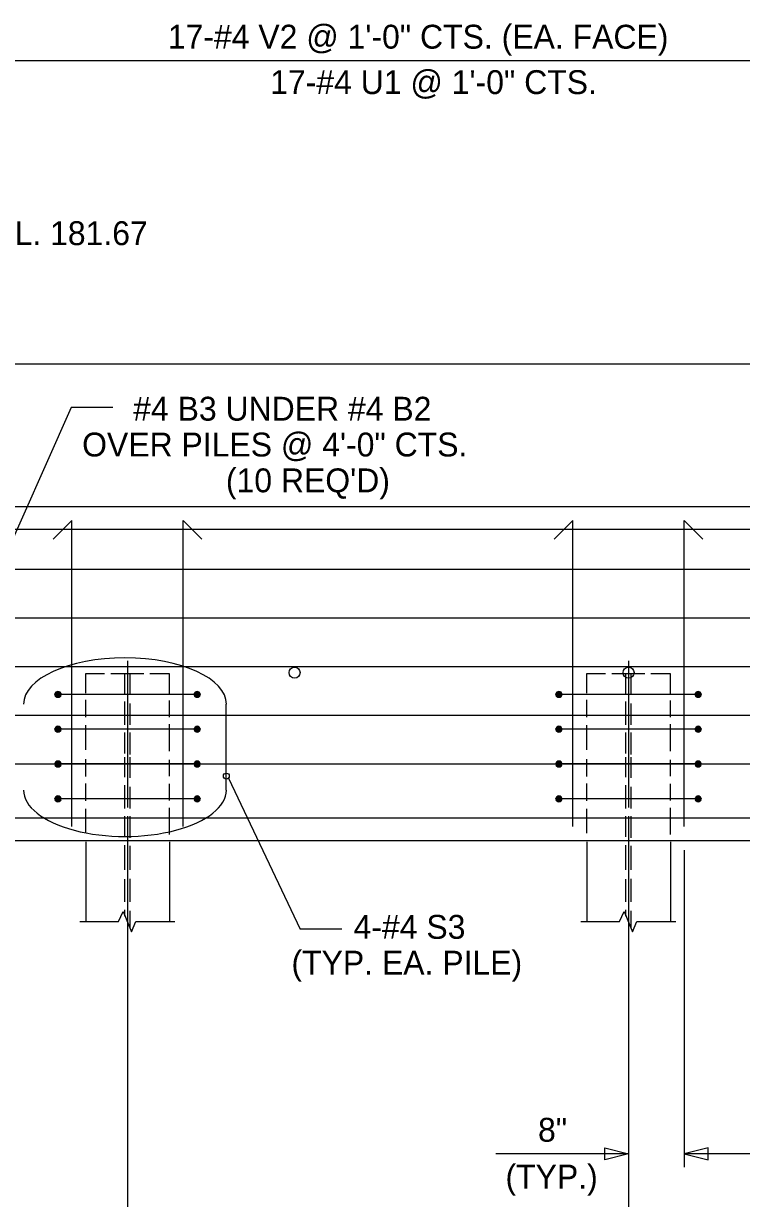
# Model space of a CAD drawing. Extents: x -41 to 251, y -169 to 237.
# Drawn here: x 105.52 to 114.12, y -40.94 to -26.87 of the extents above; entities that cross this region are included whole.
import ezdxf

# ---------------------------------------------------------------- set-up
doc = ezdxf.new("R2010")
doc.units = 0
for name, color, linetype in [('Arrowhead Terminators', 7, 'Continuous'), ('Arrowhead Terminators CELL', 7, 'Continuous'), ('Dimension Lines', 7, 'Continuous'), ('Dimension Lines CELL', 7, 'Continuous'), ('Mis Object Lines', 7, 'Continuous'), ('Rebar Lines', 7, 'Continuous'), ('Rebar Lines CELL', 7, 'Continuous'), ('Text', 7, 'Continuous')]:
    doc.layers.add(name, color=color, linetype=linetype)

msp = doc.modelspace()

# ---------------------------------------------------------------- linework, layer by layer
at = {"layer": 'Arrowhead Terminators'}
msp.add_lwpolyline([(113.716, -40.331), (113.43, -40.402), (113.716, -40.474)], close=True, dxfattribs=at)
at = {"layer": 'Arrowhead Terminators CELL'}
msp.add_lwpolyline([(112.763, -40.402), (112.477, -40.474), (112.477, -40.331)], close=True, dxfattribs=at)
at = {"layer": 'Dimension Lines'}
for p, q in [((102.846, -27.312), (118.763, -27.312)), ((106.087, -31.467), (104.763, -34.448)), ((106.587, -31.467), (106.087, -31.467)), ((107.946, -36.047), (107.946, -35.02)), ((107.973, -35.904), (108.831, -37.714)), ((106.763, -36.652), (106.763, -43.319)), ((112.763, -36.652), (112.763, -43.001)), ((113.43, -36.767), (113.43, -40.562)), ((109.331, -37.714), (108.831, -37.714)), ((112.763, -40.402), (111.175, -40.402)), ((118.096, -40.402), (113.43, -40.402))]:
    msp.add_line(p, q, dxfattribs=at)
for centre, start_param, end_param in [((106.732, -35.02), 3.141593, 6.283185), ((106.732, -36.047), 0, 3.141593)]:
    msp.add_ellipse(centre, major_axis=(-1.215, 0), ratio=0.457627, start_param=start_param, end_param=end_param, dxfattribs=at)
at = {"layer": 'Dimension Lines CELL'}
msp.add_circle((107.946, -35.88), 0.0353, dxfattribs=at)
at = {"layer": 'Mis Object Lines'}
for p, q in [((102.555, -30.944), (125.46, -30.944)), ((99.263, -32.652), (138.263, -32.652)), ((102.851, -36.652), (132.579, -36.652))]:
    msp.add_line(p, q, dxfattribs=at)
at = {"layer": 'Rebar Lines'}
for p, q in [((99.97, -32.923), (137.551, -32.923)), ((106.096, -32.819), (105.872, -33.043)), ((106.096, -36.485), (106.096, -32.819)), ((107.43, -36.485), (107.43, -32.819)), ((107.43, -32.819), (107.654, -33.043)), ((112.096, -32.819), (111.872, -33.043)), ((112.096, -36.485), (112.096, -32.819)), ((113.43, -36.485), (113.43, -32.819)), ((113.43, -32.819), (113.654, -33.043)), ((99.512, -33.402), (117.387, -33.402)), ((99.512, -33.986), (117.387, -33.986)), ((99.512, -34.569), (117.387, -34.569)), ((106.763, -34.501), (106.763, -36.257)), ((112.763, -34.501), (112.763, -36.257)), ((106.732, -34.895), (106.732, -34.652)), ((106.795, -34.901), (106.795, -34.652)), ((112.732, -34.895), (112.732, -34.652)), ((112.795, -34.901), (112.795, -34.652)), ((106.732, -35.267), (106.732, -34.988)), ((106.795, -35.267), (106.795, -35.011)), ((112.732, -35.267), (112.732, -34.988)), ((112.795, -35.267), (112.795, -35.011)), ((99.512, -35.152), (117.387, -35.152)), ((106.732, -35.609), (106.732, -35.36)), ((106.795, -35.621), (106.795, -35.36)), ((112.732, -35.609), (112.732, -35.36)), ((112.795, -35.621), (112.795, -35.36)), ((99.512, -35.735), (117.387, -35.735)), ((106.732, -35.895), (106.732, -35.652)), ((106.795, -35.901), (106.795, -35.652)), ((112.732, -35.895), (112.732, -35.652)), ((112.795, -35.901), (112.795, -35.652)), ((106.732, -36.267), (106.732, -35.988)), ((106.795, -36.267), (106.795, -36.011)), ((112.732, -36.267), (112.732, -35.988)), ((112.795, -36.267), (112.795, -36.011)), ((99.97, -36.381), (137.551, -36.381)), ((106.732, -36.609), (106.732, -36.36)), ((106.763, -36.362), (106.763, -36.652)), ((106.795, -36.621), (106.795, -36.36)), ((112.732, -36.609), (112.732, -36.36)), ((112.763, -36.362), (112.763, -36.652)), ((112.795, -36.621), (112.795, -36.36)), ((106.262, -36.669), (106.262, -37.621)), ((106.732, -37.004), (106.732, -36.708)), ((106.763, -36.722), (106.763, -37.928)), ((106.795, -37.004), (106.795, -36.714)), ((107.264, -36.669), (107.264, -37.621)), ((112.262, -36.669), (112.262, -37.621)), ((112.732, -37.004), (112.732, -36.708)), ((112.763, -36.722), (112.763, -37.928)), ((112.795, -37.004), (112.795, -36.714)), ((113.264, -36.669), (113.264, -37.621)), ((106.732, -37.388), (106.732, -37.115)), ((106.795, -37.388), (106.795, -37.109)), ((112.732, -37.388), (112.732, -37.115)), ((112.795, -37.388), (112.795, -37.109)), ((106.732, -37.556), (106.732, -37.481)), ((106.795, -37.705), (106.795, -37.492)), ((112.732, -37.556), (112.732, -37.481)), ((112.795, -37.705), (112.795, -37.492))]:
    msp.add_line(p, q, dxfattribs=at)
for points in [[(106.262, -34.886), (106.262, -34.652), (106.485, -34.652)], [(106.561, -34.652), (106.96, -34.652)], [(107.03, -34.652), (107.262, -34.652), (107.262, -34.899)], [(112.262, -34.886), (112.262, -34.652), (112.485, -34.652)], [(112.561, -34.652), (112.96, -34.652)], [(113.03, -34.652), (113.262, -34.652), (113.262, -34.899)], [(106.262, -35.176), (106.262, -34.968)], [(107.262, -34.974), (107.262, -35.173)], [(112.262, -35.176), (112.262, -34.968)], [(113.262, -34.974), (113.262, -35.173)], [(106.262, -35.564), (106.262, -35.272)], [(107.262, -35.259), (107.262, -35.58)], [(112.262, -35.564), (112.262, -35.272)], [(113.262, -35.259), (113.262, -35.58)], [(106.262, -35.886), (106.262, -35.678)], [(107.262, -35.684), (107.262, -35.883)], [(112.262, -35.886), (112.262, -35.678)], [(113.262, -35.684), (113.262, -35.883)], [(106.262, -36.176), (106.262, -35.968)], [(107.262, -35.974), (107.262, -36.173)], [(112.262, -36.176), (112.262, -35.968)], [(113.262, -35.974), (113.262, -36.173)], [(106.262, -36.564), (106.262, -36.272)], [(107.262, -36.259), (107.262, -36.58)], [(112.262, -36.564), (112.262, -36.272)], [(113.262, -36.259), (113.262, -36.58)], [(106.193, -37.622), (106.655, -37.622), (106.71, -37.502), (106.812, -37.747), (106.863, -37.622), (107.33, -37.622)], [(112.193, -37.622), (112.655, -37.622), (112.71, -37.502), (112.812, -37.747), (112.863, -37.622), (113.33, -37.622)]]:
    msp.add_lwpolyline(points, dxfattribs=at)
for centre in [(108.763, -34.641), (112.763, -34.641)]:
    msp.add_circle(centre, 0.066, dxfattribs=at)
at = {"layer": 'Rebar Lines CELL'}
for p, q in [((107.596, -34.902), (105.93, -34.902)), ((113.596, -34.902), (111.93, -34.902)), ((107.596, -35.319), (105.93, -35.319)), ((113.596, -35.319), (111.93, -35.319)), ((107.596, -35.735), (105.93, -35.735)), ((113.596, -35.735), (111.93, -35.735)), ((107.596, -36.152), (105.93, -36.152)), ((113.596, -36.152), (111.93, -36.152))]:
    msp.add_line(p, q, dxfattribs=at)
for points in [[(105.93, -34.867), (105.916, -34.87), (105.905, -34.877), (105.897, -34.889), (105.894, -34.902), (105.897, -34.916), (105.905, -34.927), (105.916, -34.935), (105.93, -34.937), (105.943, -34.935), (105.955, -34.927), (105.962, -34.916), (105.965, -34.902), (105.962, -34.889), (105.955, -34.877), (105.943, -34.87), (105.93, -34.867), (105.93, -34.902), (105.93, -34.937), (105.916, -34.935), (105.93, -34.902), (105.905, -34.927), (105.897, -34.916), (105.93, -34.902), (105.894, -34.902), (105.897, -34.889), (105.93, -34.902), (105.905, -34.877), (105.916, -34.87), (105.93, -34.902), (105.943, -34.87), (105.955, -34.877), (105.93, -34.902), (105.962, -34.889), (105.965, -34.902), (105.93, -34.902), (105.962, -34.916), (105.955, -34.927), (105.93, -34.902), (105.943, -34.935)], [(107.596, -34.867), (107.583, -34.87), (107.571, -34.877), (107.564, -34.889), (107.561, -34.902), (107.564, -34.916), (107.571, -34.927), (107.583, -34.935), (107.596, -34.937), (107.61, -34.935), (107.621, -34.927), (107.629, -34.916), (107.632, -34.902), (107.629, -34.889), (107.621, -34.877), (107.61, -34.87), (107.596, -34.867), (107.596, -34.902), (107.596, -34.937), (107.583, -34.935), (107.596, -34.902), (107.571, -34.927), (107.564, -34.916), (107.596, -34.902), (107.561, -34.902), (107.564, -34.889), (107.596, -34.902), (107.571, -34.877), (107.583, -34.87), (107.596, -34.902), (107.61, -34.87), (107.621, -34.877), (107.596, -34.902), (107.629, -34.889), (107.632, -34.902), (107.596, -34.902), (107.629, -34.916), (107.621, -34.927), (107.596, -34.902), (107.61, -34.935)], [(111.93, -34.867), (111.916, -34.87), (111.905, -34.877), (111.897, -34.889), (111.894, -34.902), (111.897, -34.916), (111.905, -34.927), (111.916, -34.935), (111.93, -34.937), (111.943, -34.935), (111.955, -34.927), (111.962, -34.916), (111.965, -34.902), (111.962, -34.889), (111.955, -34.877), (111.943, -34.87), (111.93, -34.867), (111.93, -34.902), (111.93, -34.937), (111.916, -34.935), (111.93, -34.902), (111.905, -34.927), (111.897, -34.916), (111.93, -34.902), (111.894, -34.902), (111.897, -34.889), (111.93, -34.902), (111.905, -34.877), (111.916, -34.87), (111.93, -34.902), (111.943, -34.87), (111.955, -34.877), (111.93, -34.902), (111.962, -34.889), (111.965, -34.902), (111.93, -34.902), (111.962, -34.916), (111.955, -34.927), (111.93, -34.902), (111.943, -34.935)], [(113.596, -34.867), (113.583, -34.87), (113.571, -34.877), (113.564, -34.889), (113.561, -34.902), (113.564, -34.916), (113.571, -34.927), (113.583, -34.935), (113.596, -34.937), (113.61, -34.935), (113.621, -34.927), (113.629, -34.916), (113.632, -34.902), (113.629, -34.889), (113.621, -34.877), (113.61, -34.87), (113.596, -34.867), (113.596, -34.902), (113.596, -34.937), (113.583, -34.935), (113.596, -34.902), (113.571, -34.927), (113.564, -34.916), (113.596, -34.902), (113.561, -34.902), (113.564, -34.889), (113.596, -34.902), (113.571, -34.877), (113.583, -34.87), (113.596, -34.902), (113.61, -34.87), (113.621, -34.877), (113.596, -34.902), (113.629, -34.889), (113.632, -34.902), (113.596, -34.902), (113.629, -34.916), (113.621, -34.927), (113.596, -34.902), (113.61, -34.935)], [(105.93, -35.284), (105.916, -35.286), (105.905, -35.294), (105.897, -35.305), (105.894, -35.319), (105.897, -35.332), (105.905, -35.344), (105.916, -35.351), (105.93, -35.354), (105.943, -35.351), (105.955, -35.344), (105.962, -35.332), (105.965, -35.319), (105.962, -35.305), (105.955, -35.294), (105.943, -35.286), (105.93, -35.284), (105.93, -35.319), (105.93, -35.354), (105.916, -35.351), (105.93, -35.319), (105.905, -35.344), (105.897, -35.332), (105.93, -35.319), (105.894, -35.319), (105.897, -35.305), (105.93, -35.319), (105.905, -35.294), (105.916, -35.286), (105.93, -35.319), (105.943, -35.286), (105.955, -35.294), (105.93, -35.319), (105.962, -35.305), (105.965, -35.319), (105.93, -35.319), (105.962, -35.332), (105.955, -35.344), (105.93, -35.319), (105.943, -35.351)], [(107.596, -35.284), (107.583, -35.286), (107.571, -35.294), (107.564, -35.305), (107.561, -35.319), (107.564, -35.332), (107.571, -35.344), (107.583, -35.351), (107.596, -35.354), (107.61, -35.351), (107.621, -35.344), (107.629, -35.332), (107.632, -35.319), (107.629, -35.305), (107.621, -35.294), (107.61, -35.286), (107.596, -35.284), (107.596, -35.319), (107.596, -35.354), (107.583, -35.351), (107.596, -35.319), (107.571, -35.344), (107.564, -35.332), (107.596, -35.319), (107.561, -35.319), (107.564, -35.305), (107.596, -35.319), (107.571, -35.294), (107.583, -35.286), (107.596, -35.319), (107.61, -35.286), (107.621, -35.294), (107.596, -35.319), (107.629, -35.305), (107.632, -35.319), (107.596, -35.319), (107.629, -35.332), (107.621, -35.344), (107.596, -35.319), (107.61, -35.351)], [(111.93, -35.284), (111.916, -35.286), (111.905, -35.294), (111.897, -35.305), (111.894, -35.319), (111.897, -35.332), (111.905, -35.344), (111.916, -35.351), (111.93, -35.354), (111.943, -35.351), (111.955, -35.344), (111.962, -35.332), (111.965, -35.319), (111.962, -35.305), (111.955, -35.294), (111.943, -35.286), (111.93, -35.284), (111.93, -35.319), (111.93, -35.354), (111.916, -35.351), (111.93, -35.319), (111.905, -35.344), (111.897, -35.332), (111.93, -35.319), (111.894, -35.319), (111.897, -35.305), (111.93, -35.319), (111.905, -35.294), (111.916, -35.286), (111.93, -35.319), (111.943, -35.286), (111.955, -35.294), (111.93, -35.319), (111.962, -35.305), (111.965, -35.319), (111.93, -35.319), (111.962, -35.332), (111.955, -35.344), (111.93, -35.319), (111.943, -35.351)], [(113.596, -35.284), (113.583, -35.286), (113.571, -35.294), (113.564, -35.305), (113.561, -35.319), (113.564, -35.332), (113.571, -35.344), (113.583, -35.351), (113.596, -35.354), (113.61, -35.351), (113.621, -35.344), (113.629, -35.332), (113.632, -35.319), (113.629, -35.305), (113.621, -35.294), (113.61, -35.286), (113.596, -35.284), (113.596, -35.319), (113.596, -35.354), (113.583, -35.351), (113.596, -35.319), (113.571, -35.344), (113.564, -35.332), (113.596, -35.319), (113.561, -35.319), (113.564, -35.305), (113.596, -35.319), (113.571, -35.294), (113.583, -35.286), (113.596, -35.319), (113.61, -35.286), (113.621, -35.294), (113.596, -35.319), (113.629, -35.305), (113.632, -35.319), (113.596, -35.319), (113.629, -35.332), (113.621, -35.344), (113.596, -35.319), (113.61, -35.351)], [(105.93, -35.7), (105.916, -35.703), (105.905, -35.711), (105.897, -35.722), (105.894, -35.735), (105.897, -35.749), (105.905, -35.76), (105.916, -35.768), (105.93, -35.771), (105.943, -35.768), (105.955, -35.76), (105.962, -35.749), (105.965, -35.735), (105.962, -35.722), (105.955, -35.711), (105.943, -35.703), (105.93, -35.7), (105.93, -35.735), (105.93, -35.771), (105.916, -35.768), (105.93, -35.735), (105.905, -35.76), (105.897, -35.749), (105.93, -35.735), (105.894, -35.735), (105.897, -35.722), (105.93, -35.735), (105.905, -35.711), (105.916, -35.703), (105.93, -35.735), (105.943, -35.703), (105.955, -35.711), (105.93, -35.735), (105.962, -35.722), (105.965, -35.735), (105.93, -35.735), (105.962, -35.749), (105.955, -35.76), (105.93, -35.735), (105.943, -35.768)], [(107.596, -35.7), (107.583, -35.703), (107.571, -35.711), (107.564, -35.722), (107.561, -35.735), (107.564, -35.749), (107.571, -35.76), (107.583, -35.768), (107.596, -35.771), (107.61, -35.768), (107.621, -35.76), (107.629, -35.749), (107.632, -35.735), (107.629, -35.722), (107.621, -35.711), (107.61, -35.703), (107.596, -35.7), (107.596, -35.735), (107.596, -35.771), (107.583, -35.768), (107.596, -35.735), (107.571, -35.76), (107.564, -35.749), (107.596, -35.735), (107.561, -35.735), (107.564, -35.722), (107.596, -35.735), (107.571, -35.711), (107.583, -35.703), (107.596, -35.735), (107.61, -35.703), (107.621, -35.711), (107.596, -35.735), (107.629, -35.722), (107.632, -35.735), (107.596, -35.735), (107.629, -35.749), (107.621, -35.76), (107.596, -35.735), (107.61, -35.768)], [(111.93, -35.7), (111.916, -35.703), (111.905, -35.711), (111.897, -35.722), (111.894, -35.735), (111.897, -35.749), (111.905, -35.76), (111.916, -35.768), (111.93, -35.771), (111.943, -35.768), (111.955, -35.76), (111.962, -35.749), (111.965, -35.735), (111.962, -35.722), (111.955, -35.711), (111.943, -35.703), (111.93, -35.7), (111.93, -35.735), (111.93, -35.771), (111.916, -35.768), (111.93, -35.735), (111.905, -35.76), (111.897, -35.749), (111.93, -35.735), (111.894, -35.735), (111.897, -35.722), (111.93, -35.735), (111.905, -35.711), (111.916, -35.703), (111.93, -35.735), (111.943, -35.703), (111.955, -35.711), (111.93, -35.735), (111.962, -35.722), (111.965, -35.735), (111.93, -35.735), (111.962, -35.749), (111.955, -35.76), (111.93, -35.735), (111.943, -35.768)], [(113.596, -35.7), (113.583, -35.703), (113.571, -35.711), (113.564, -35.722), (113.561, -35.735), (113.564, -35.749), (113.571, -35.76), (113.583, -35.768), (113.596, -35.771), (113.61, -35.768), (113.621, -35.76), (113.629, -35.749), (113.632, -35.735), (113.629, -35.722), (113.621, -35.711), (113.61, -35.703), (113.596, -35.7), (113.596, -35.735), (113.596, -35.771), (113.583, -35.768), (113.596, -35.735), (113.571, -35.76), (113.564, -35.749), (113.596, -35.735), (113.561, -35.735), (113.564, -35.722), (113.596, -35.735), (113.571, -35.711), (113.583, -35.703), (113.596, -35.735), (113.61, -35.703), (113.621, -35.711), (113.596, -35.735), (113.629, -35.722), (113.632, -35.735), (113.596, -35.735), (113.629, -35.749), (113.621, -35.76), (113.596, -35.735), (113.61, -35.768)], [(105.93, -36.117), (105.916, -36.12), (105.905, -36.127), (105.897, -36.139), (105.894, -36.152), (105.897, -36.166), (105.905, -36.177), (105.916, -36.185), (105.93, -36.187), (105.943, -36.185), (105.955, -36.177), (105.962, -36.166), (105.965, -36.152), (105.962, -36.139), (105.955, -36.127), (105.943, -36.12), (105.93, -36.117), (105.93, -36.152), (105.93, -36.187), (105.916, -36.185), (105.93, -36.152), (105.905, -36.177), (105.897, -36.166), (105.93, -36.152), (105.894, -36.152), (105.897, -36.139), (105.93, -36.152), (105.905, -36.127), (105.916, -36.12), (105.93, -36.152), (105.943, -36.12), (105.955, -36.127), (105.93, -36.152), (105.962, -36.139), (105.965, -36.152), (105.93, -36.152), (105.962, -36.166), (105.955, -36.177), (105.93, -36.152), (105.943, -36.185)], [(107.596, -36.117), (107.583, -36.12), (107.571, -36.127), (107.564, -36.139), (107.561, -36.152), (107.564, -36.166), (107.571, -36.177), (107.583, -36.185), (107.596, -36.187), (107.61, -36.185), (107.621, -36.177), (107.629, -36.166), (107.632, -36.152), (107.629, -36.139), (107.621, -36.127), (107.61, -36.12), (107.596, -36.117), (107.596, -36.152), (107.596, -36.187), (107.583, -36.185), (107.596, -36.152), (107.571, -36.177), (107.564, -36.166), (107.596, -36.152), (107.561, -36.152), (107.564, -36.139), (107.596, -36.152), (107.571, -36.127), (107.583, -36.12), (107.596, -36.152), (107.61, -36.12), (107.621, -36.127), (107.596, -36.152), (107.629, -36.139), (107.632, -36.152), (107.596, -36.152), (107.629, -36.166), (107.621, -36.177), (107.596, -36.152), (107.61, -36.185)], [(111.93, -36.117), (111.916, -36.12), (111.905, -36.127), (111.897, -36.139), (111.894, -36.152), (111.897, -36.166), (111.905, -36.177), (111.916, -36.185), (111.93, -36.187), (111.943, -36.185), (111.955, -36.177), (111.962, -36.166), (111.965, -36.152), (111.962, -36.139), (111.955, -36.127), (111.943, -36.12), (111.93, -36.117), (111.93, -36.152), (111.93, -36.187), (111.916, -36.185), (111.93, -36.152), (111.905, -36.177), (111.897, -36.166), (111.93, -36.152), (111.894, -36.152), (111.897, -36.139), (111.93, -36.152), (111.905, -36.127), (111.916, -36.12), (111.93, -36.152), (111.943, -36.12), (111.955, -36.127), (111.93, -36.152), (111.962, -36.139), (111.965, -36.152), (111.93, -36.152), (111.962, -36.166), (111.955, -36.177), (111.93, -36.152), (111.943, -36.185)], [(113.596, -36.117), (113.583, -36.12), (113.571, -36.127), (113.564, -36.139), (113.561, -36.152), (113.564, -36.166), (113.571, -36.177), (113.583, -36.185), (113.596, -36.187), (113.61, -36.185), (113.621, -36.177), (113.629, -36.166), (113.632, -36.152), (113.629, -36.139), (113.621, -36.127), (113.61, -36.12), (113.596, -36.117), (113.596, -36.152), (113.596, -36.187), (113.583, -36.185), (113.596, -36.152), (113.571, -36.177), (113.564, -36.166), (113.596, -36.152), (113.561, -36.152), (113.564, -36.139), (113.596, -36.152), (113.571, -36.127), (113.583, -36.12), (113.596, -36.152), (113.61, -36.12), (113.621, -36.127), (113.596, -36.152), (113.629, -36.139), (113.632, -36.152), (113.596, -36.152), (113.629, -36.166), (113.621, -36.177), (113.596, -36.152), (113.61, -36.185)]]:
    msp.add_lwpolyline(points, dxfattribs=at)

# ---------------------------------------------------------------- texts
at = {"layer": 'Text'}
for s, p in [('17-#4 V2 @ 1\'-0" CTS. (EA. FACE)', (107.245, -27.169)), ('17-#4 U1 @ 1\'-0" CTS.', (108.471, -27.713)), ('EL. 181.67', (105.155, -29.522)), ('#4 B3 UNDER #4 B2', (106.831, -31.624)), ('OVER PILES @ 4\'-0" CTS.', (106.219, -32.053)), ("(10 REQ'D)", (107.941, -32.482)), ('4-#4 S3', (109.47, -37.829)), ('(TYP. EA. PILE)', (108.726, -38.258)), ('8"', (111.679, -40.259)), ('(TYP.)', (111.289, -40.82))]:
    msp.add_text(s, height=0.286, dxfattribs=at).set_placement(p)

doc.saveas('drawing.dxf')
